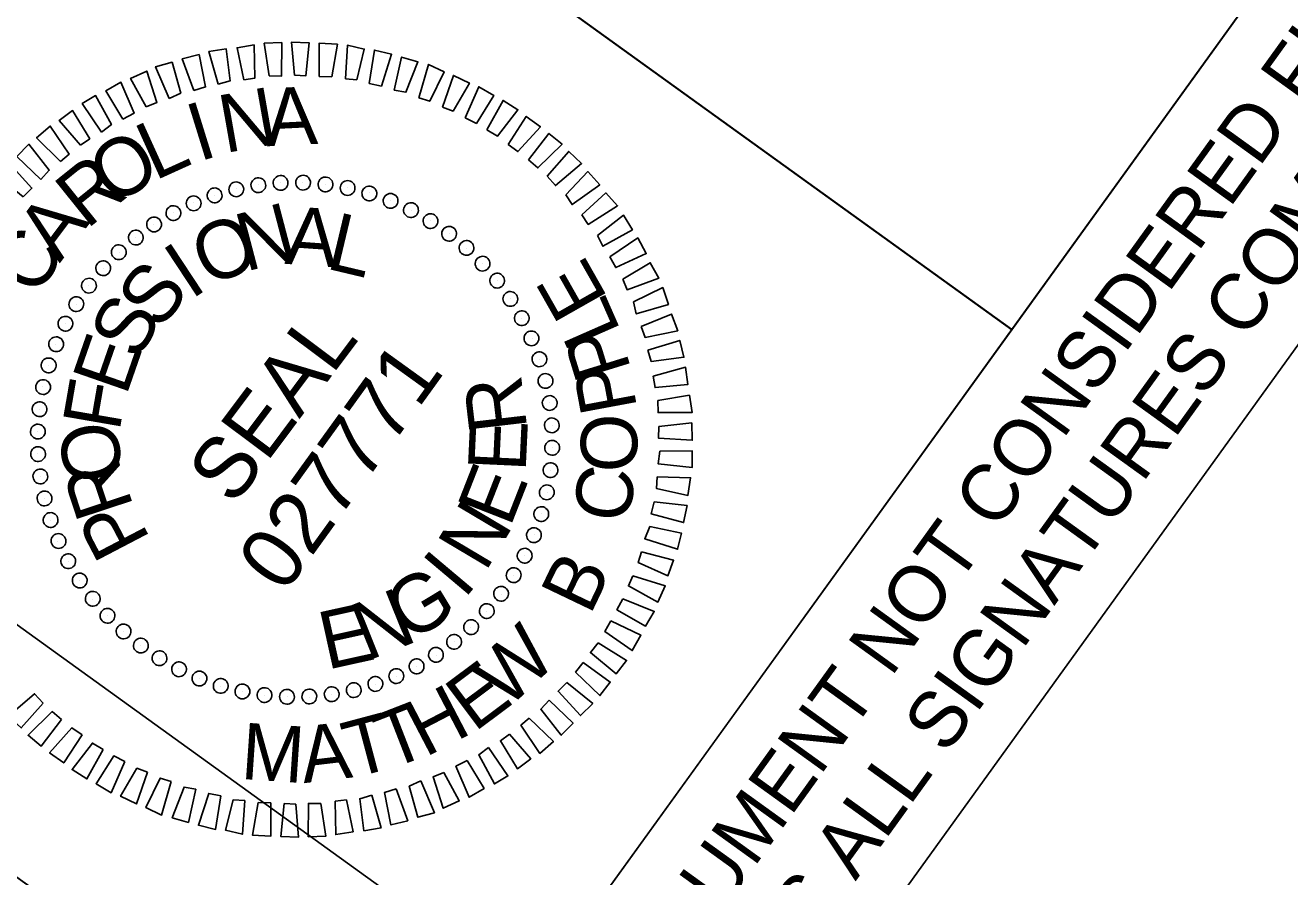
# Model space of a CAD drawing. Extents: x 2186840 to 2191350, y 386817 to 390793.
# Drawn here: x 2190437.4 to 2190560.6, y 388573.6 to 388656.7 of the extents above; entities that cross this region are included whole.
import ezdxf

# ---------------------------------------------------------------- set-up
doc = ezdxf.new("R2010")
doc.units = 0
for name, color, linetype in [('Sheet Layout Plan Border', 7, 'Continuous'), ('Sheet Plan CELL', 7, 'Continuous'), ('Sheet Professional Seal CELL', 7, 'Continuous'), ('Sheet Sticker Exception Certification CELL', 7, 'Continuous')]:
    doc.layers.add(name, color=color, linetype=linetype)

msp = doc.modelspace()

# ---------------------------------------------------------------- linework, layer by layer
at = {"layer": 'Sheet Layout Plan Border'}
msp.add_lwpolyline([(2190469.75, 387008.54), (2191313.6, 388178.64), (2190637.85, 388665.97), (2190536.83, 388525.9), (2190366.46, 388648.77), (2189623.63, 387618.74)], close=True, dxfattribs=at)
at = {"layer": 'Sheet Plan CELL'}
msp.add_line((2190442.28, 388692.79), (2190533.51, 388627.02), dxfattribs=at)
for points in [[(2190442.28, 388692.79), (2190500.76, 388773.9), (2190592.02, 388708.09), (2190533.54, 388626.98)], [(2190444.54, 386965.06), (2189592.91, 387579.2), (2190353.28, 388633.62), (2190475, 388545.85), (2190592.02, 388708.09), (2191321.95, 388181.69)], [(2190383.76, 388611.64), (2190442.28, 388692.79), (2190533.54, 388626.98), (2190475, 388545.85)]]:
    msp.add_lwpolyline(points, close=True, dxfattribs=at)
at = {"layer": 'Sheet Professional Seal CELL'}
for p, q in [((2190457.94, 388640.72), (2190457.94, 388640.72)), ((2190460.07, 388641.1), (2190460.07, 388641.1)), ((2190462.28, 388641.35), (2190462.28, 388641.35)), ((2190464.43, 388641.34), (2190464.43, 388641.34)), ((2190466.65, 388641.16), (2190466.65, 388641.16)), ((2190468.81, 388640.83), (2190468.81, 388640.83)), ((2190470.9, 388640.31), (2190470.9, 388640.31)), ((2190453.76, 388639.36), (2190453.76, 388639.36)), ((2190455.83, 388640.09), (2190455.83, 388640.09)), ((2190472.96, 388639.57), (2190472.96, 388639.57)), ((2190451.81, 388638.36), (2190451.81, 388638.36)), ((2190474.98, 388638.61), (2190474.98, 388638.61)), ((2190449.91, 388637.27), (2190449.91, 388637.27)), ((2190476.9, 388637.59), (2190476.9, 388637.59)), ((2190448.11, 388635.97), (2190448.11, 388635.97)), ((2190478.71, 388636.35), (2190478.71, 388636.35)), ((2190446.52, 388634.53), (2190446.52, 388634.53)), ((2190480.41, 388634.94), (2190480.41, 388634.94)), ((2190444.98, 388632.99), (2190444.98, 388632.99)), ((2190481.95, 388633.4), (2190481.95, 388633.4)), ((2190483.39, 388631.8), (2190483.39, 388631.8)), ((2190443.57, 388631.3), (2190443.57, 388631.3)), ((2190442.32, 388629.48), (2190442.32, 388629.48)), ((2190484.68, 388630.01), (2190484.68, 388630.01)), ((2190485.78, 388628.11), (2190485.78, 388628.11)), ((2190441.31, 388627.57), (2190441.31, 388627.57)), ((2190440.35, 388625.55), (2190440.35, 388625.55)), ((2190486.77, 388626.16), (2190486.77, 388626.16)), ((2190439.6, 388623.49), (2190439.6, 388623.49)), ((2190487.5, 388624.09), (2190487.5, 388624.09)), ((2190488.13, 388621.97), (2190488.13, 388621.97)), ((2190439.08, 388621.4), (2190439.08, 388621.4)), ((2190488.51, 388619.85), (2190488.51, 388619.85)), ((2190438.75, 388619.24), (2190438.75, 388619.24)), ((2190438.57, 388617.02), (2190438.57, 388617.02)), ((2190488.76, 388617.63), (2190488.76, 388617.63)), ((2190463.66, 388616.25), (2190463.66, 388616.25)), ((2190438.56, 388614.87), (2190438.56, 388614.87)), ((2190488.75, 388615.48), (2190488.75, 388615.48)), ((2190488.57, 388613.27), (2190488.57, 388613.27)), ((2190438.82, 388612.66), (2190438.82, 388612.66)), ((2190488.24, 388611.1), (2190488.24, 388611.1)), ((2190439.2, 388610.53), (2190439.2, 388610.53)), ((2190439.83, 388608.41), (2190439.83, 388608.41)), ((2190487.72, 388609.01), (2190487.72, 388609.01)), ((2190440.55, 388606.35), (2190440.55, 388606.35)), ((2190486.98, 388606.96), (2190486.98, 388606.96)), ((2190486.02, 388604.94), (2190486.02, 388604.94)), ((2190441.55, 388604.4), (2190441.55, 388604.4)), ((2190442.65, 388602.5), (2190442.65, 388602.5)), ((2190485, 388603.02), (2190485, 388603.02)), ((2190483.76, 388601.2), (2190483.76, 388601.2)), ((2190443.94, 388600.7), (2190443.94, 388600.7)), ((2190445.38, 388599.11), (2190445.38, 388599.11)), ((2190482.35, 388599.51), (2190482.35, 388599.51)), ((2190446.92, 388597.56), (2190446.92, 388597.56)), ((2190480.81, 388597.97), (2190480.81, 388597.97)), ((2190448.62, 388596.16), (2190448.62, 388596.16)), ((2190479.21, 388596.53), (2190479.21, 388596.53)), ((2190450.43, 388594.91), (2190450.43, 388594.91)), ((2190477.42, 388595.23), (2190477.42, 388595.23)), ((2190452.35, 388593.9), (2190452.35, 388593.9)), ((2190475.52, 388594.14), (2190475.52, 388594.14)), ((2190454.37, 388592.93), (2190454.37, 388592.93)), ((2190471.5, 388592.41), (2190471.5, 388592.41)), ((2190473.57, 388593.14), (2190473.57, 388593.14)), ((2190456.42, 388592.19), (2190456.42, 388592.19)), ((2190458.51, 388591.67), (2190458.51, 388591.67)), ((2190460.68, 388591.34), (2190460.68, 388591.34)), ((2190462.89, 388591.16), (2190462.89, 388591.16)), ((2190465.04, 388591.15), (2190465.04, 388591.15)), ((2190467.26, 388591.4), (2190467.26, 388591.4)), ((2190469.38, 388591.78), (2190469.38, 388591.78))]:
    msp.add_line(p, q, dxfattribs=at)
for points in [[(2190456.18, 388650.93), (2190455.27, 388654.11), (2190456.95, 388654.38), (2190457.35, 388651.26)], [(2190458.66, 388651.36), (2190458.01, 388654.48), (2190459.68, 388654.75), (2190459.74, 388651.5)], [(2190461.14, 388651.73), (2190460.66, 388654.91), (2190462.37, 388654.97), (2190462.36, 388651.71)], [(2190463.6, 388651.81), (2190463.33, 388655.02), (2190465.06, 388654.94), (2190464.72, 388651.74)], [(2190466.02, 388651.66), (2190466.03, 388654.92), (2190467.8, 388654.82), (2190467.24, 388651.64)], [(2190468.57, 388651.43), (2190468.78, 388654.72), (2190470.42, 388654.34), (2190469.69, 388651.36)], [(2190470.89, 388650.98), (2190471.4, 388654.25), (2190473.08, 388653.84), (2190472.08, 388650.74)], [(2190451.4, 388649.51), (2190450.07, 388652.62), (2190451.68, 388653.06), (2190452.53, 388650.05)], [(2190453.81, 388650.29), (2190452.67, 388653.4), (2190454.32, 388653.81), (2190454.94, 388650.65)], [(2190473.33, 388650.34), (2190474.06, 388653.57), (2190475.64, 388653.11), (2190474.47, 388650.13)], [(2190475.74, 388649.58), (2190476.68, 388652.85), (2190478.19, 388652.13), (2190476.8, 388649.25)], [(2190449.16, 388648.72), (2190447.64, 388651.48), (2190449.21, 388652.2), (2190450.21, 388649.14)], [(2190478.04, 388648.67), (2190479.11, 388651.78), (2190480.67, 388651.03), (2190479.07, 388648.29)], [(2190446.89, 388647.52), (2190445.22, 388650.26), (2190446.7, 388651.11), (2190447.97, 388648.09)], [(2190480.25, 388647.63), (2190481.58, 388650.67), (2190483.05, 388649.8), (2190481.34, 388647.09)], [(2190444.8, 388646.25), (2190442.92, 388649.03), (2190444.22, 388649.81), (2190445.76, 388646.98)], [(2190482.37, 388646.47), (2190483.95, 388649.34), (2190485.39, 388648.42), (2190483.4, 388645.85)], [(2190442.75, 388644.96), (2190440.68, 388647.38), (2190441.99, 388648.34), (2190443.65, 388645.6)], [(2190484.43, 388645.04), (2190486.21, 388647.77), (2190487.59, 388646.77), (2190485.4, 388644.34)], [(2190440.82, 388643.39), (2190438.48, 388645.7), (2190439.8, 388646.84), (2190441.64, 388644.09)], [(2190486.43, 388643.54), (2190488.41, 388646.12), (2190489.69, 388645.07), (2190487.34, 388642.76)], [(2190438.88, 388641.64), (2190436.55, 388643.88), (2190437.72, 388645.07), (2190439.71, 388642.53)], [(2190488.23, 388641.94), (2190490.34, 388644.36), (2190491.6, 388643.2), (2190489.05, 388641.03)], [(2190437.16, 388639.93), (2190434.64, 388641.99), (2190435.85, 388643.16), (2190438.02, 388640.79)], [(2190490.06, 388640.12), (2190492.2, 388642.4), (2190493.37, 388641.12), (2190490.68, 388639.18)], [(2190491.63, 388638.19), (2190493.97, 388640.32), (2190495.1, 388639.07), (2190492.25, 388637.25)], [(2190493.14, 388636.18), (2190495.68, 388638.16), (2190496.56, 388636.73), (2190493.67, 388635.12)], [(2190494.34, 388634.08), (2190497.08, 388635.92), (2190497.9, 388634.4), (2190494.93, 388633.03)], [(2190495.62, 388631.92), (2190498.3, 388633.5), (2190499.12, 388631.99), (2190496.04, 388630.88)], [(2190496.66, 388629.69), (2190499.51, 388631.08), (2190500.06, 388629.45), (2190496.92, 388628.52)], [(2190497.4, 388627.3), (2190500.36, 388628.5), (2190500.98, 388626.88), (2190497.79, 388626.22)], [(2190498.07, 388624.98), (2190501.17, 388625.94), (2190501.58, 388624.29), (2190498.39, 388623.88)], [(2190498.58, 388622.45), (2190501.74, 388623.31), (2190501.94, 388621.63), (2190498.76, 388621.33)], [(2190499.04, 388620.08), (2190502.11, 388620.58), (2190502.38, 388618.91), (2190499.05, 388618.9)], [(2190499.12, 388617.55), (2190502.33, 388617.89), (2190502.39, 388616.19), (2190499.1, 388616.4)], [(2190499.23, 388615.14), (2190502.38, 388615.15), (2190502.39, 388613.54), (2190499.07, 388613.89)], [(2190498.96, 388612.62), (2190502.23, 388612.54), (2190501.97, 388610.82), (2190498.89, 388611.5)], [(2190498.67, 388610.18), (2190501.88, 388609.83), (2190501.54, 388608.17), (2190498.39, 388609.02)], [(2190498.24, 388607.78), (2190501.35, 388607.13), (2190500.96, 388605.57), (2190497.75, 388606.59)], [(2190497.45, 388605.32), (2190500.56, 388604.5), (2190500.02, 388602.98), (2190497.12, 388604.26)], [(2190496.58, 388602.99), (2190499.75, 388602), (2190499.04, 388600.42), (2190496.17, 388602)], [(2190495.62, 388600.73), (2190498.68, 388599.5), (2190497.84, 388598.08), (2190495.04, 388599.67)], [(2190494.46, 388598.6), (2190497.38, 388597.18), (2190496.54, 388595.68), (2190493.88, 388597.54)], [(2190493.2, 388596.43), (2190495.98, 388594.73), (2190494.98, 388593.42), (2190492.46, 388595.49)], [(2190491.75, 388594.51), (2190494.39, 388592.61), (2190493.39, 388591.3), (2190491.01, 388593.57)], [(2190490.17, 388592.57), (2190492.69, 388590.51), (2190491.48, 388589.35), (2190489.31, 388591.72)], [(2190439.1, 388590.57), (2190436.98, 388588.15), (2190435.72, 388589.3), (2190438.27, 388591.47)], [(2190440.9, 388588.96), (2190438.92, 388586.38), (2190437.64, 388587.43), (2190439.98, 388589.74)], [(2190488.44, 388590.86), (2190490.77, 388588.62), (2190489.61, 388587.43), (2190487.62, 388589.97)], [(2190486.5, 388589.11), (2190488.85, 388586.81), (2190487.53, 388585.66), (2190485.69, 388588.41)], [(2190442.9, 388587.46), (2190441.12, 388584.73), (2190439.74, 388585.73), (2190441.92, 388588.16)], [(2190484.57, 388587.55), (2190486.65, 388585.13), (2190485.34, 388584.16), (2190483.68, 388586.9)], [(2190444.96, 388586.04), (2190443.38, 388583.17), (2190441.94, 388584.08), (2190443.92, 388586.66)], [(2190482.53, 388586.25), (2190484.41, 388583.47), (2190483.1, 388582.69), (2190481.57, 388585.52)], [(2190447.08, 388584.88), (2190445.74, 388581.83), (2190444.28, 388582.7), (2190445.99, 388585.42)], [(2190480.44, 388584.98), (2190482.1, 388582.24), (2190480.63, 388581.39), (2190479.35, 388584.41)], [(2190449.29, 388583.84), (2190448.21, 388580.73), (2190446.66, 388581.48), (2190448.26, 388584.21)], [(2190478.16, 388583.79), (2190479.68, 388581.02), (2190478.12, 388580.31), (2190477.12, 388583.37)], [(2190451.58, 388582.92), (2190450.65, 388579.65), (2190449.13, 388580.37), (2190450.53, 388583.25)], [(2190454, 388582.16), (2190453.27, 388578.93), (2190451.69, 388579.39), (2190452.85, 388582.37)], [(2190475.93, 388582.99), (2190477.26, 388579.88), (2190475.64, 388579.44), (2190474.8, 388582.45)], [(2190456.43, 388581.52), (2190455.92, 388578.25), (2190454.24, 388578.66), (2190455.25, 388581.76)], [(2190458.76, 388581.07), (2190458.54, 388577.78), (2190456.9, 388578.16), (2190457.64, 388581.14)], [(2190468.67, 388581.14), (2190469.32, 388578.02), (2190467.64, 388577.75), (2190467.58, 388581)], [(2190471.14, 388581.58), (2190472.05, 388578.39), (2190470.38, 388578.12), (2190469.98, 388581.24)], [(2190473.51, 388582.21), (2190474.66, 388579.1), (2190473.01, 388578.69), (2190472.39, 388581.85)], [(2190461.31, 388580.84), (2190461.3, 388577.58), (2190459.52, 388577.69), (2190460.08, 388580.86)], [(2190463.73, 388580.7), (2190464, 388577.48), (2190462.27, 388577.56), (2190462.61, 388580.77)], [(2190466.19, 388580.77), (2190466.67, 388577.59), (2190464.96, 388577.53), (2190464.97, 388580.79)]]:
    msp.add_lwpolyline(points, close=True, dxfattribs=at)
for centre, major_axis in [((2190460.09, 388641.07), (-0.103, 0.713)), ((2190462.26, 388641.29), (-0.04, 0.719)), ((2190464.45, 388641.32), (0.023, 0.72)), ((2190466.63, 388641.15), (0.085, 0.715)), ((2190468.79, 388640.8), (0.147, 0.705)), ((2190455.83, 388640.08), (-0.225, 0.684)), ((2190457.94, 388640.67), (-0.164, 0.701)), ((2190470.91, 388640.26), (0.208, 0.689)), ((2190472.98, 388639.54), (0.267, 0.669)), ((2190451.81, 388638.35), (-0.34, 0.635)), ((2190453.78, 388639.3), (-0.284, 0.662)), ((2190474.97, 388638.64), (0.325, 0.643)), ((2190449.93, 388637.24), (-0.394, 0.602)), ((2190476.88, 388637.57), (0.379, 0.612)), ((2190448.15, 388635.96), (-0.445, 0.566)), ((2190478.69, 388636.33), (0.431, 0.577)), ((2190480.38, 388634.95), (0.48, 0.537)), ((2190446.49, 388634.53), (-0.493, 0.525)), ((2190481.95, 388633.42), (0.525, 0.493)), ((2190444.97, 388632.97), (-0.537, 0.48)), ((2190443.58, 388631.27), (-0.577, 0.431)), ((2190483.37, 388631.76), (0.566, 0.445)), ((2190484.65, 388629.98), (0.602, 0.394)), ((2190442.35, 388629.47), (-0.612, 0.379)), ((2190441.28, 388627.56), (-0.643, 0.325)), ((2190485.77, 388628.1), (0.635, 0.34)), ((2190486.71, 388626.13), (0.662, 0.284)), ((2190440.38, 388625.56), (-0.669, 0.267)), ((2190439.65, 388623.5), (-0.689, 0.208)), ((2190487.49, 388624.09), (0.684, 0.225)), ((2190439.11, 388621.38), (-0.705, 0.147)), ((2190488.08, 388621.98), (0.701, 0.164)), ((2190488.49, 388619.83), (0.713, 0.103)), ((2190438.76, 388619.22), (-0.715, 0.085)), ((2190488.7, 388617.65), (0.719, 0.04)), ((2190438.6, 388617.04), (-0.72, 0.023)), ((2190488.73, 388615.46), (0.72, -0.023)), ((2190438.62, 388614.85), (-0.719, -0.04)), ((2190438.84, 388612.67), (-0.713, -0.103)), ((2190488.57, 388613.28), (0.715, -0.085)), ((2190439.25, 388610.52), (-0.701, -0.164)), ((2190488.21, 388611.12), (0.705, -0.147)), ((2190487.67, 388609), (0.689, -0.208)), ((2190439.84, 388608.42), (-0.684, -0.225)), ((2190440.61, 388606.37), (-0.662, -0.284)), ((2190486.95, 388606.94), (0.669, -0.267)), ((2190486.05, 388604.94), (0.643, -0.325)), ((2190441.56, 388604.4), (-0.635, -0.34)), ((2190442.68, 388602.52), (-0.602, -0.394)), ((2190484.98, 388603.04), (0.612, -0.379)), ((2190443.95, 388600.74), (-0.566, -0.445)), ((2190483.75, 388601.23), (0.577, -0.431)), ((2190445.38, 388599.08), (-0.525, -0.493)), ((2190482.36, 388599.54), (0.537, -0.48)), ((2190480.83, 388597.97), (0.493, -0.525)), ((2190446.95, 388597.55), (-0.48, -0.537)), ((2190479.17, 388596.54), (0.445, -0.566)), ((2190448.64, 388596.17), (-0.431, -0.577)), ((2190477.4, 388595.27), (0.394, -0.602)), ((2190450.45, 388594.94), (-0.379, -0.612)), ((2190452.36, 388593.86), (-0.325, -0.643)), ((2190475.52, 388594.15), (0.34, -0.635)), ((2190454.35, 388592.96), (-0.267, -0.669)), ((2190473.54, 388593.2), (0.284, -0.662)), ((2190456.42, 388592.24), (-0.208, -0.689)), ((2190458.54, 388591.7), (-0.147, -0.705)), ((2190467.24, 388591.43), (0.103, -0.713)), ((2190469.39, 388591.83), (0.164, -0.701)), ((2190471.5, 388592.43), (0.225, -0.684)), ((2190460.69, 388591.35), (-0.085, -0.715)), ((2190462.88, 388591.18), (-0.023, -0.72)), ((2190465.06, 388591.21), (0.04, -0.719))]:
    msp.add_ellipse(centre, major_axis=major_axis, ratio=0.999708, dxfattribs=at)
at = {"layer": 'Sheet Sticker Exception Certification CELL'}
for p, q in [((2190475, 388545.85), (2190592.01, 388708.1)), ((2190475, 388545.85), (2190592.01, 388708.1)), ((2190611.07, 388694.36), (2190494.06, 388532.11)), ((2190611.07, 388694.36), (2190494.06, 388532.11))]:
    msp.add_line(p, q, dxfattribs=at)

# ---------------------------------------------------------------- texts
at = {"layer": 'Sheet Professional Seal CELL'}
for s, height, rotation, p in [('N', 5.64, 10.0208, (2190456.81, 388644.19)), ('A', 5.64, 2.819, (2190460.93, 388644.86)), ('I', 5.64, 17.222, (2190454.29, 388643.35)), ('L', 5.64, 24.4227, (2190449.98, 388641.47)), ('O', 5.64, 31.623, (2190445.9, 388638.98)), ('R', 5.64, 38.8229, (2190443.34, 388636.7)), ('A', 5.64, 53.2222, (2190440.72, 388633.42)), ('N', 5.64, 14.6785, (2190458.83, 388632.62)), ('O', 5.64, 24.0353, (2190455.24, 388631.08)), ('A', 5.64, 355.9621, (2190462.6, 388633.41)), ('L', 5.64, 346.6027, (2190466.54, 388632.98)), ('C', 5.64, 60.4217, (2190438.65, 388630.04)), ('I', 5.64, 33.3914, (2190453.51, 388629.86)), ('S', 5.64, 52.1022, (2190450.42, 388626.79)), ('E', 5.5, 119.5477, (2190494.22, 388630)), ('S', 5.64, 61.4575, (2190448.36, 388623.84)), ('L', 5.5, 113.7375, (2190495.46, 388626.84)), ('SEAL', 5.998, 53.2018, (2190457.68, 388609.66)), ('E', 5.64, 70.8129, (2190447.19, 388620.42)), ('P', 5.5, 107.1545, (2190496.46, 388623.12)), ('027771', 5.998, 54.2018, (2190462.61, 388601.11)), ('P', 5.5, 100.5715, (2190497.03, 388619.32)), ('F', 5.64, 80.1689, (2190446.54, 388616.95)), ('R', 5.64, 96.6833, (2190486.31, 388617.3)), ('O', 5.5, 89.867, (2190497.02, 388613.07)), ('O', 5.64, 98.8831, (2190447, 388612.55)), ('E', 5.64, 87.3259, (2190486.14, 388613.05)), ('R', 5.64, 108.2415, (2190447.96, 388609.7)), ('E', 5.64, 68.6136, (2190484.62, 388607.61)), ('C', 5.5, 80.9943, (2190496.13, 388607.96)), ('N', 5.64, 59.2582, (2190482.21, 388603.25)), ('P', 5.64, 117.6007, (2190449.62, 388606.53)), ('I', 5.64, 49.903, (2190480.13, 388600.62)), ('B', 5.5, 64.4224, (2190492.42, 388599.04)), ('G', 5.64, 31.1921, (2190474.76, 388596.42)), ('N', 5.64, 21.8358, (2190470.71, 388594.65)), ('E', 5.64, 12.4787, (2190466.76, 388593.8)), ('W', 5.5, 43.3711, (2190484.32, 388589.86)), ('E', 5.5, 36.7881, (2190481.15, 388587.67)), ('H', 5.5, 27.5433, (2190476.34, 388585.23)), ('T', 5.5, 21.2466, (2190472.86, 388584.03)), ('M', 5.5, 356.0881, (2190458.29, 388583.18)), ('A', 5.5, 6.764, (2190464.51, 388582.75)), ('T', 5.5, 14.9498, (2190469.27, 388583.21))]:
    msp.add_text(s, height=height, rotation=rotation, dxfattribs=at).set_placement(p)
at = {"layer": 'Sheet Sticker Exception Certification CELL'}
for s, p in [('DOCUMENT NOT CONSIDERED FINAL', (2190495.72, 388556.89)), ('DOCUMENT NOT CONSIDERED FINAL', (2190495.72, 388556.89)), ('UNLESS ALL SIGNATURES COMPLETED', (2190499.89, 388547.63)), ('UNLESS ALL SIGNATURES COMPLETED', (2190499.89, 388547.63))]:
    msp.add_text(s, height=5.5, rotation=54.2018, dxfattribs=at).set_placement(p)

doc.saveas('drawing.dxf')
